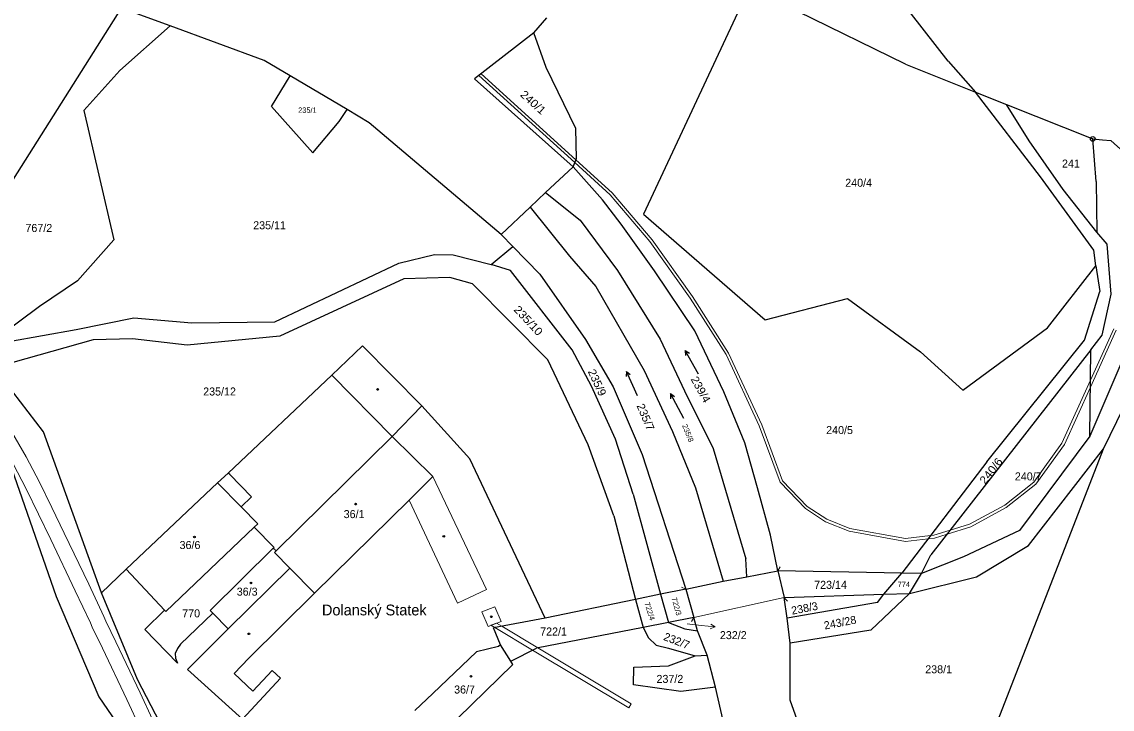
# Model space of a CAD drawing. Extents: x -701211 to -698780, y -1014269 to -1012378.
# Drawn here: x -701029.9 to -700798.3, y -1012820.3 to -1012674.3 of the extents above; entities that cross this region are included whole.
import ezdxf
from ezdxf.enums import TextEntityAlignment as Align

# ---------------------------------------------------------------- set-up
doc = ezdxf.new("R2010")
doc.units = 0
doc.header["$LTSCALE"] = 0.68
for name, color, linetype, lineweight in [('1', 7, 'Continuous', 25), ('13', 7, 'Continuous', 13), ('3', 7, 'Continuous', 25), ('4', 7, 'Continuous', 13), ('5', 7, 'Continuous', 25), ('7', 7, 'Continuous', 13), ('8', 7, 'Continuous', 25)]:
    doc.layers.add(name, color=color, linetype=linetype, lineweight=lineweight)
doc.layers.add('2', color=7, linetype='Continuous')

msp = doc.modelspace()

# ---------------------------------------------------------------- linework, layer by layer
at = {"layer": '1'}
for p, q in [((-700864.73, -1012644.37), (-700897.88, -1012715.22)), ((-700833.17, -1012682.68), (-700854.85, -1012654.77)), ((-701048.22, -1012733.88), (-701008.69, -1012671.43)), ((-700998.37, -1012675.21), (-701008.69, -1012671.43)), ((-700921.16, -1012676.68), (-700918.37, -1012673.46)), ((-700842.22, -1012683.31), (-700865.09, -1012672.14)), ((-701009.06, -1012684.68), (-700998.37, -1012675.21)), ((-700978.39, -1012682.54), (-700998.37, -1012675.21)), ((-700921.16, -1012676.68), (-700933.76, -1012686.48)), ((-700918.49, -1012684.05), (-700921.16, -1012676.68)), ((-700972.86, -1012685.83), (-700978.39, -1012682.54)), ((-700833.17, -1012682.68), (-700827.37, -1012689.3)), ((-701016.73, -1012693.2), (-701009.06, -1012684.68)), ((-700912.19, -1012696.98), (-700918.49, -1012684.05)), ((-700842.22, -1012683.31), (-700827.37, -1012689.3)), ((-700976.82, -1012692.34), (-700972.86, -1012685.83)), ((-700960.81, -1012692.99), (-700972.86, -1012685.83)), ((-700933.76, -1012686.48), (-700912.81, -1012705.13)), ((-700813.58, -1012707.27), (-700827.37, -1012689.3)), ((-700827.37, -1012689.3), (-700820.78, -1012691.92)), ((-700976.82, -1012692.34), (-700968.04, -1012702.16)), ((-700820.78, -1012691.92), (-700802.46, -1012699.19)), ((-700815.99, -1012699.6), (-700820.78, -1012691.92)), ((-701016.73, -1012693.2), (-701010.36, -1012720.66)), ((-700962.46, -1012695.54), (-700960.81, -1012692.99)), ((-700956.13, -1012695.78), (-700960.81, -1012692.99)), ((-700968.04, -1012702.16), (-700962.46, -1012695.54)), ((-700928.09, -1012719.47), (-700956.13, -1012695.78)), ((-700912.1, -1012703.38), (-700912.19, -1012696.98)), ((-700801.75, -1012708.23), (-700802.46, -1012699.19)), ((-700802.46, -1012699.19), (-700800.35, -1012699.37)), ((-700800.35, -1012699.37), (-700798.64, -1012699.51)), ((-700808.77, -1012709.96), (-700815.99, -1012699.6)), ((-700798.64, -1012699.51), (-700780.48, -1012715.84)), ((-700912.81, -1012705.13), (-700912.1, -1012703.38)), ((-700918.64, -1012710.61), (-700912.81, -1012705.13)), ((-700906.59, -1012712.16), (-700912.81, -1012705.13)), ((-700802.23, -1012722.86), (-700813.58, -1012707.27)), ((-700801.75, -1012708.23), (-700801.59, -1012719.02)), ((-700921.93, -1012713.69), (-700918.64, -1012710.61)), ((-700918.64, -1012710.61), (-700911.33, -1012716.46)), ((-700801.59, -1012719.02), (-700808.77, -1012709.96)), ((-700902.63, -1012717.29), (-700906.59, -1012712.16)), ((-700928.09, -1012719.47), (-700921.93, -1012713.69)), ((-700921.93, -1012713.69), (-700913.58, -1012724.11)), ((-700897.88, -1012715.22), (-700872.02, -1012737.63)), ((-700911.33, -1012716.46), (-700903.36, -1012727.13)), ((-700895.51, -1012727.2), (-700902.63, -1012717.29)), ((-700928.09, -1012719.47), (-700925.58, -1012722.06)), ((-700799.37, -1012721.58), (-700801.59, -1012719.02)), ((-701010.36, -1012720.66), (-701018.08, -1012729.34)), ((-700930.23, -1012725.91), (-700925.58, -1012722.06)), ((-700925.58, -1012722.06), (-700919.88, -1012727.94)), ((-700798.56, -1012732.21), (-700799.37, -1012721.58)), ((-700949.78, -1012725.56), (-700942.26, -1012723.72)), ((-700942.26, -1012723.72), (-700938.3, -1012723.81)), ((-700938.3, -1012723.81), (-700930.23, -1012725.91)), ((-700913.58, -1012724.11), (-700907.98, -1012730.58)), ((-700801.78, -1012726.19), (-700802.23, -1012722.86)), ((-700976.16, -1012738.07), (-700949.78, -1012725.56)), ((-700926.12, -1012727.17), (-700930.23, -1012725.91)), ((-700912.98, -1012744), (-700926.12, -1012727.17)), ((-700903.36, -1012727.13), (-700894.3, -1012741.74)), ((-700886.97, -1012739.98), (-700895.51, -1012727.2)), ((-700812.04, -1012739.34), (-700801.78, -1012726.19)), ((-700801.78, -1012726.19), (-700800.97, -1012731.6)), ((-700800.19, -1012765.01), (-700780.71, -1012725.02)), ((-701018.08, -1012729.34), (-701026.15, -1012734.82)), ((-700948.78, -1012728.94), (-700975.06, -1012741.09)), ((-700938.96, -1012728.62), (-700948.78, -1012728.94)), ((-700934.19, -1012729.98), (-700938.96, -1012728.62)), ((-700919.88, -1012727.94), (-700910.14, -1012741.83)), ((-700918.17, -1012746.14), (-700934.19, -1012729.98)), ((-700907.98, -1012730.58), (-700897.72, -1012748.4)), ((-700804.21, -1012741.96), (-700800.97, -1012731.6)), ((-700872.02, -1012737.63), (-700854.55, -1012733.13)), ((-700854.55, -1012733.13), (-700839.06, -1012744.39)), ((-701026.15, -1012734.82), (-701035.16, -1012741.52)), ((-701006.05, -1012737.17), (-700993.75, -1012738.25)), ((-700993.75, -1012738.25), (-700976.16, -1012738.07)), ((-700975.06, -1012741.09), (-700994.73, -1012742.98)), ((-700880.76, -1012752.95), (-700886.97, -1012739.98)), ((-700830.05, -1012752.59), (-700812.04, -1012739.34)), ((-701014.71, -1012741.85), (-701035.74, -1012747.8)), ((-701006.34, -1012741.63), (-701014.71, -1012741.85)), ((-700994.73, -1012742.98), (-701006.34, -1012741.63)), ((-700964.07, -1012749.41), (-700957.49, -1012743.16)), ((-700957.49, -1012743.16), (-700944.93, -1012755.88)), ((-700910.14, -1012741.83), (-700904.29, -1012751.83)), ((-700894.3, -1012741.74), (-700889.17, -1012752.73)), ((-700824.92, -1012767.81), (-700804.21, -1012741.96)), ((-700908.93, -1012751.7), (-700912.98, -1012744)), ((-700839.06, -1012744.39), (-700830.05, -1012752.59)), ((-700802.83, -1012743.98), (-700836.85, -1012787.56)), ((-700803.07, -1012762.31), (-700802.83, -1012743.98)), ((-700795.24, -1012744.03), (-700803.07, -1012762.31)), ((-701025.26, -1012761.42), (-701035.74, -1012747.8)), ((-700909.57, -1012764.15), (-700918.17, -1012746.14)), ((-700986.05, -1012770.16), (-700964.07, -1012749.41)), ((-700897.72, -1012748.4), (-700891.69, -1012761.37)), ((-700903.79, -1012762.95), (-700908.93, -1012751.7)), ((-700904.29, -1012751.83), (-700898.17, -1012766.23)), ((-700889.17, -1012752.73), (-700883.04, -1012764.97)), ((-700876.34, -1012763.75), (-700880.76, -1012752.95)), ((-700944.93, -1012755.88), (-700934.74, -1012767.14)), ((-701012.98, -1012795.59), (-701025.26, -1012761.42)), ((-700891.69, -1012761.37), (-700886.83, -1012773.34)), ((-700904.17, -1012779.24), (-700909.57, -1012764.15)), ((-700900.05, -1012774.62), (-700903.79, -1012762.95)), ((-700873.64, -1012773.29), (-700876.34, -1012763.75)), ((-700803.07, -1012762.31), (-700818.02, -1012782.4)), ((-701033.16, -1012765.88), (-701022.57, -1012796.35)), ((-700898.17, -1012766.23), (-700888.86, -1012794.81)), ((-700883.04, -1012764.97), (-700876.12, -1012788.39)), ((-700823.05, -1012823.84), (-700800.19, -1012765.01)), ((-700816.13, -1012785.55), (-700800.19, -1012765.01)), ((-700918.75, -1012800.96), (-700934.74, -1012767.14)), ((-700824.92, -1012767.81), (-700843.01, -1012791.42)), ((-700986.05, -1012770.16), (-700988.35, -1012772.23)), ((-700985.69, -1012770.49), (-700986.05, -1012770.16)), ((-700981.08, -1012775.23), (-700985.69, -1012770.49)), ((-701007.72, -1012790.55), (-700988.35, -1012772.23)), ((-700886.83, -1012773.34), (-700880.94, -1012793.1)), ((-700870.85, -1012783.38), (-700873.64, -1012773.29)), ((-700981.08, -1012775.23), (-700983.3, -1012777.34)), ((-700900.05, -1012774.62), (-700894.22, -1012795.91)), ((-700983.3, -1012777.34), (-700979.75, -1012780.94)), ((-700904.17, -1012779.24), (-700899.54, -1012797.01)), ((-700980.51, -1012781.67), (-700999.31, -1012799.54)), ((-700979.75, -1012780.94), (-700980.51, -1012781.67)), ((-700976.29, -1012785.95), (-700980.51, -1012781.67)), ((-700818.02, -1012782.4), (-700829.91, -1012787.98)), ((-700869.32, -1012790.94), (-700870.85, -1012783.38)), ((-700989.84, -1012799.38), (-700976.47, -1012786.12)), ((-700976.47, -1012786.12), (-700976.29, -1012785.95)), ((-700976.47, -1012786.12), (-700975.87, -1012786.71)), ((-700975.87, -1012786.71), (-700976.2, -1012787.06)), ((-700976.2, -1012787.06), (-700972.93, -1012790.38)), ((-700827.12, -1012792.21), (-700816.13, -1012785.55)), ((-700875.89, -1012792.2), (-700876.12, -1012788.39)), ((-700838.83, -1012791.5), (-700836.85, -1012787.56)), ((-700829.91, -1012787.98), (-700838.83, -1012791.5)), ((-701007.72, -1012790.55), (-701012.98, -1012795.59)), ((-700999.58, -1012799.26), (-701007.72, -1012790.55)), ((-700972.93, -1012790.38), (-700986.06, -1012803.22)), ((-700875.89, -1012792.2), (-700869.32, -1012790.94)), ((-700843.01, -1012791.42), (-700869.32, -1012790.94)), ((-700869.32, -1012790.94), (-700868, -1012796.63)), ((-700846.79, -1012795.91), (-700843.01, -1012791.42)), ((-700838.83, -1012791.5), (-700843.01, -1012791.42)), ((-700841.34, -1012795.73), (-700838.83, -1012791.5)), ((-700888.86, -1012794.81), (-700880.94, -1012793.1)), ((-700880.94, -1012793.1), (-700875.89, -1012792.2)), ((-700841.34, -1012795.73), (-700827.12, -1012792.21)), ((-701022.57, -1012796.35), (-701013.51, -1012817.71)), ((-701005.28, -1012814.01), (-701012.98, -1012795.59)), ((-700894.22, -1012795.91), (-700899.54, -1012797.01)), ((-700888.86, -1012794.81), (-700894.22, -1012795.91)), ((-700894.22, -1012795.91), (-700892.53, -1012801.91)), ((-700888.86, -1012794.81), (-700887.15, -1012800.87)), ((-700868, -1012796.63), (-700846.79, -1012795.91)), ((-700867.31, -1012801.01), (-700868, -1012796.63)), ((-700841.34, -1012795.73), (-700849.56, -1012803.51)), ((-700848.13, -1012797.63), (-700846.79, -1012795.91)), ((-700846.79, -1012795.91), (-700841.34, -1012795.73)), ((-700899.54, -1012797.01), (-700918.75, -1012800.96)), ((-700899.54, -1012797.01), (-700897.95, -1012802.96)), ((-700848.13, -1012797.63), (-700867.31, -1012801.01)), ((-701003.76, -1012803.41), (-700999.58, -1012799.26)), ((-700999.31, -1012799.54), (-700999.58, -1012799.26)), ((-700989.31, -1012799.91), (-700996.17, -1012806.52)), ((-700989.31, -1012799.91), (-700989.84, -1012799.38)), ((-700986.06, -1012803.22), (-700989.31, -1012799.91)), ((-700918.75, -1012800.96), (-700929.71, -1012803.02)), ((-700887.15, -1012800.87), (-700892.53, -1012801.91)), ((-700886.4, -1012803.64), (-700887.15, -1012800.87)), ((-700866.7, -1012806.29), (-700867.31, -1012801.01)), ((-701003.76, -1012803.41), (-700996.83, -1012810.57)), ((-700928.21, -1012806.64), (-700929.71, -1012803.02)), ((-700897.95, -1012802.96), (-700920.59, -1012807.33)), ((-700892.53, -1012801.91), (-700897.95, -1012802.96)), ((-700897.95, -1012802.96), (-700896.76, -1012805.17)), ((-700892.53, -1012801.91), (-700889.1, -1012803.28)), ((-700889.1, -1012803.28), (-700886.4, -1012803.64)), ((-700849.56, -1012803.51), (-700866.7, -1012806.29)), ((-700896.76, -1012805.17), (-700895.18, -1012806.7)), ((-700884.33, -1012808.82), (-700886.4, -1012803.64)), ((-700996.8, -1012807.42), (-700997.29, -1012808.49)), ((-700996.17, -1012806.52), (-700996.8, -1012807.42)), ((-700926.05, -1012810.14), (-700928.21, -1012806.64)), ((-700926.05, -1012810.14), (-700920.59, -1012807.33)), ((-700895.18, -1012806.7), (-700892.52, -1012807.38)), ((-700892.52, -1012807.38), (-700886.9, -1012808.95)), ((-700866.7, -1012818.38), (-700866.7, -1012806.29)), ((-700997.29, -1012808.49), (-700997.24, -1012809.46)), ((-700997.24, -1012809.46), (-700996.83, -1012810.57)), ((-700925.63, -1012810.81), (-700926.05, -1012810.14)), ((-700892.53, -1012811.13), (-700886.9, -1012808.95)), ((-700886.9, -1012808.95), (-700884.33, -1012808.82)), ((-700882.58, -1012815.63), (-700884.33, -1012808.82)), ((-700937.26, -1012822.19), (-700925.63, -1012810.81)), ((-700899.96, -1012815.14), (-700899.92, -1012811.4)), ((-700899.92, -1012811.4), (-700892.53, -1012811.13)), ((-701000.52, -1012823.26), (-701005.28, -1012814.01)), ((-700889.96, -1012816.58), (-700899.96, -1012815.14)), ((-700946.4, -1012820.6), (-700942.56, -1012816.95)), ((-700882.58, -1012815.63), (-700889.96, -1012816.58)), ((-700879.16, -1012830.48), (-700882.58, -1012815.63)), ((-701013.51, -1012817.71), (-701005.43, -1012829.46)), ((-700861.58, -1012832.59), (-700866.7, -1012818.38))]:
    msp.add_line(p, q, dxfattribs=at)
for points in [[(-700802.83, -1012743.98), (-700800.43, -1012740.9), (-700798.56, -1012732.21)], [(-701032.65, -1012742.22), (-701018.33, -1012739.7), (-701006.05, -1012737.17)], [(-700928.21, -1012806.64), (-700928.65, -1012807.03), (-700933.31, -1012808.11), (-700942.56, -1012816.95)]]:
    msp.add_lwpolyline(points, dxfattribs=at)
at = {"layer": '13'}
for points in [[(-700797.99, -1012739.55), (-700802.91, -1012750.41), (-700808.99, -1012763.83), (-700814.97, -1012772.09), (-700821.15, -1012776.97), (-700828.6, -1012781.02), (-700832.75, -1012782.31), (-700836.21, -1012783.39), (-700836.91, -1012783.46), (-700842.22, -1012784.07), (-700854.03, -1012781.94), (-700858.93, -1012779.98), (-700863.07, -1012777.26), (-700868.34, -1012771.81), (-700872.75, -1012759.91), (-700879.81, -1012744.7), (-700887.47, -1012732.69), (-700896.02, -1012720.64), (-700904.49, -1012710.64), (-700912.21, -1012703.65), (-700932.35, -1012685.38), (-700932.83, -1012685.76), (-700912.45, -1012704.24), (-700904.93, -1012711.06), (-700896.5, -1012721), (-700887.97, -1012733.03), (-700880.33, -1012744.98), (-700873.31, -1012760.15), (-700868.86, -1012772.13), (-700863.45, -1012777.72), (-700859.21, -1012780.52), (-700854.19, -1012782.52), (-700842.24, -1012784.67), (-700837.42, -1012784.13), (-700836.09, -1012783.97), (-700833.4, -1012783.14), (-700828.36, -1012781.58), (-700820.81, -1012777.47), (-700814.53, -1012772.51), (-700808.47, -1012764.13), (-700802.93, -1012751.91), (-700797.45, -1012739.79)], [(-701002.1, -1012822.49), (-701004.74, -1012816.87), (-701009.91, -1012805.98), (-701012.02, -1012801.61), (-701012.43, -1012800.64), (-701015.67, -1012793.79), (-701020.86, -1012782.93), (-701023.48, -1012777.48), (-701026.14, -1012772.08), (-701028.98, -1012766.71), (-701032.07, -1012761.35)], [(-701031.74, -1012768.23), (-701028.96, -1012773.52), (-701026.31, -1012778.88), (-701023.7, -1012784.29), (-701018.53, -1012795.15), (-701015.31, -1012801.94), (-701014.9, -1012802.91), (-701012.77, -1012807.34), (-701007.6, -1012818.23), (-701004.64, -1012824.49)]]:
    msp.add_lwpolyline(points, dxfattribs=at)
msp.add_lwpolyline([(-700930.24, -1012802.5), (-700929.45, -1012802.97), (-700921.45, -1012807.77), (-700901, -1012820.03), (-700900.48, -1012819.17), (-700920.32, -1012807.28), (-700927.97, -1012802.69), (-700929.06, -1012802.04)], close=True, dxfattribs=at)
at = {"layer": '3'}
for p, q in [((-700888.972, -1012744.159), (-700888.106, -1012744.74)), ((-700901.468, -1012748.588), (-700900.656, -1012749.242)), ((-700892.139, -1012753.282), (-700891.237, -1012753.909))]:
    msp.add_line(p, q, dxfattribs=at)
for points in [[(-700886.209, -1012749.144), (-700888.972, -1012744.159), (-700888.939, -1012745.202)], [(-700899.15, -1012753.795), (-700901.468, -1012748.588), (-700901.526, -1012749.63)], [(-700889.322, -1012758.58), (-700892.139, -1012753.282), (-700892.123, -1012754.38)]]:
    msp.add_lwpolyline(points, dxfattribs=at)
at = {"layer": '4'}
for p, q in [((-700951.19, -1012762.42), (-700964.07, -1012749.41)), ((-700951.19, -1012762.42), (-700944.93, -1012755.88)), ((-700951.19, -1012762.42), (-700975.87, -1012786.71)), ((-700942.56, -1012770.92), (-700951.19, -1012762.42)), ((-700942.56, -1012770.92), (-700947.65, -1012775.93)), ((-700942.56, -1012770.92), (-700931.22, -1012794.91)), ((-700988.35, -1012772.23), (-700983.3, -1012777.34)), ((-700947.65, -1012775.93), (-700967.71, -1012795.68)), ((-700947.65, -1012775.93), (-700937.32, -1012797.79)), ((-700868.865, -1012790.049), (-700869.319, -1012790.94)), ((-700937.32, -1012797.79), (-700931.22, -1012794.91)), ((-700889.787, -1012794.435), (-700888.86, -1012794.809)), ((-700887.15, -1012800.87), (-700868, -1012796.63)), ((-700867.305, -1012797.35), (-700868, -1012796.631)), ((-700929.44, -1012798.61), (-700932.15, -1012799.67)), ((-700928.11, -1012801.67), (-700929.44, -1012798.61)), ((-700930.82, -1012802.73), (-700932.15, -1012799.67)), ((-700887.695, -1012801.709), (-700887.151, -1012800.87)), ((-700994.72, -1012811.87), (-700986.06, -1012803.22)), ((-700928.11, -1012801.67), (-700930.82, -1012802.73)), ((-700984.77, -1012812.75), (-700981.68, -1012809.45)), ((-700983.03, -1012822.46), (-700994.72, -1012811.87)), ((-700984.77, -1012812.75), (-700980.81, -1012816.46)), ((-700976.72, -1012812.09), (-700977.72, -1012813.16)), ((-700974.94, -1012813.76), (-700976.72, -1012812.09)), ((-700983.03, -1012822.46), (-700974.94, -1012813.76)), ((-700980.81, -1012816.46), (-700977.72, -1012813.16))]:
    msp.add_line(p, q, dxfattribs=at)
msp.add_lwpolyline([(-700972.93, -1012790.38), (-700967.71, -1012795.68), (-700981.68, -1012809.45)], dxfattribs=at)
at = {"layer": '5'}
for centre in [(-700954.3068, -1012752.4192), (-700958.9768, -1012776.7692), (-700993.2068, -1012783.7292), (-700940.2668, -1012783.6092), (-700981.2068, -1012793.5092), (-700930.1668, -1012800.6892), (-700981.6468, -1012804.3092), (-700934.4868, -1012813.3292)]:
    msp.add_circle(centre, 0.175, dxfattribs=at)
at = {"layer": '7'}
msp.add_line((-700882.625, -1012802.844), (-700883.569, -1012802.241), dxfattribs=at)
msp.add_lwpolyline([(-700888.6, -1012802.19), (-700885.61, -1012802.53), (-700882.625, -1012802.844), (-700883.674, -1012803.237)], dxfattribs=at)
at = {"layer": '8'}
for radius in [0.5, 0.0303]:
    msp.add_circle((-700802.46, -1012699.1899), radius, dxfattribs=at)

# ---------------------------------------------------------------- texts
at = {"layer": '2'}
for s, rotation, width, p in [('240/1', 318, 1.1, (-700921.8648, -1012692.0765)), ('235/10', 313, 1.1, (-700922.9247, -1012738.3643)), ('235/9', 295, 1.05, (-700908.4591, -1012751.3023)), ('240/6', 52, 1.1, (-700823.3765, -1012770.2243))]:
    msp.add_text(s, height=1.7, rotation=rotation, dxfattribs=dict(at, width=width)).set_placement(p, align=Align.CENTER)
for s, height, p in [('235/1', 1.14, (-700969.219, -1012693.665)), ('241', 1.7, (-700807.089, -1012705.295)), ('240/4', 1.7, (-700852.17, -1012709.365)), ('767/2', 1.7, (-701026.26, -1012718.965)), ('235/11', 1.7, (-700977.26, -1012718.395)), ('235/12', 1.7, (-700987.88, -1012753.695)), ('240/5', 1.7, (-700856.22, -1012761.885)), ('240/7', 1.7, (-700816.15, -1012771.725)), ('723/14', 1.7, (-700858.14, -1012794.755)), ('774', 1.14, (-700842.57, -1012794.375)), ('722/1', 1.7, (-700916.95, -1012804.665)), ('238/1', 1.7, (-700835.18, -1012812.695)), ('36/7', 1.7, (-700935.859, -1012816.985)), ('237/2', 1.7, (-700892.25, -1012814.735))]:
    msp.add_text(s, height=height, dxfattribs=at).set_placement(p, align=Align.CENTER)
at = {"layer": '2', "width": 1.05}
for s, rotation, p in [('239/4', 299, (-700887.891, -1012750.216)), ('235/7', 293, (-700899.361, -1012755.856))]:
    msp.add_text(s, height=1.7, rotation=rotation, dxfattribs=at).set_placement(p)
at = {"layer": '2'}
for s, height, rotation, p in [('235/8', 1.14, 292, (-700888.9397, -1012761.895)), ('722/3', 1.14, 286, (-700891.3808, -1012798.6284)), ('722/4', 1.14, 288, (-700897.0612, -1012799.6874)), ('238/3', 1.7, 11, (-700863.5057, -1012799.7108)), ('243/28', 1.7, 11, (-700855.9457, -1012802.7505)), ('232/7', 1.7, 339, (-700891.0971, -1012806.5859))]:
    msp.add_text(s, height=height, rotation=rotation, dxfattribs=at).set_placement(p, align=Align.CENTER)
for s, p in [('36/1', (-700961.52, -1012779.735)), ('36/6', (-700996.37, -1012786.305)), ('36/3', (-700984.23, -1012796.195)), ('770', (-700995.81, -1012800.805)), ('232/2', (-700881.63, -1012805.435))]:
    msp.add_text(s, height=1.7, dxfattribs=at).set_placement(p)
at = {"layer": '7'}
msp.add_text('Dolanský Statek', height=2.3, dxfattribs=at).set_placement((-700955.02, -1012800.395), align=Align.CENTER)

doc.saveas('drawing.dxf')
